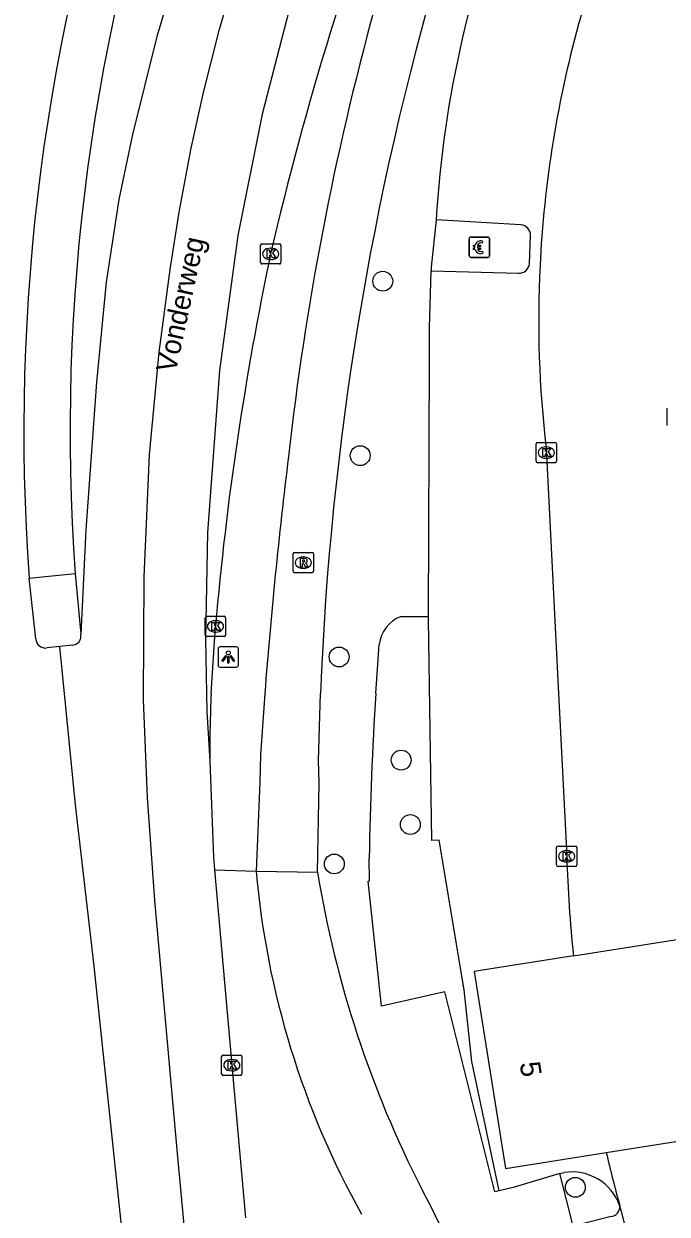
# Model space of a CAD drawing. Extents: x 160676 to 161153, y 383244 to 383713.
# Drawn here: x 160675.8 to 160707.5, y 383474.3 to 383533 of the extents above; entities that cross this region are included whole.
import ezdxf

# ---------------------------------------------------------------- set-up
doc = ezdxf.new("R2010")
doc.units = 0
for name, color, linetype in [('IMGEO_Berm_open', 7, 'Continuous'), ('IMGEO_Betaalautomaat', 7, 'Continuous'), ('IMGEO_Boom', 7, 'Continuous'), ('IMGEO_Fietspad_gesloten', 7, 'Continuous'), ('IMGEO_Kolk', 7, 'Continuous'), ('IMGEO_Lichtpunt', 7, 'Continuous'), ('IMGEO_Openbare_ruimte_label', 7, 'Continuous'), ('IMGEO_Pand', 7, 'Continuous'), ('IMGEO_Pand_nummerreeks', 7, 'Continuous'), ('IMGEO_Parkeervlak_open', 7, 'Continuous'), ('IMGEO_Rijbaan_lokaal_gesloten', 7, 'Continuous'), ('IMGEO_Rijbaan_lokaal_open', 7, 'Continuous'), ('IMGEO_Rioolput', 7, 'Continuous'), ('IMGEO_Verkeerseiland_open', 7, 'Continuous'), ('IMGEO_Voetpad_open', 7, 'Continuous')]:
    doc.layers.add(name, color=color, linetype=linetype)

msp = doc.modelspace()

# ---------------------------------------------------------------- linework, layer by layer
at = {"layer": 'IMGEO_Berm_open'}
msp.add_lwpolyline([(160685.215, 383491.312), (160687.262, 383491.252)], dxfattribs=at)
at = {"layer": 'IMGEO_Betaalautomaat'}
for p, q in [((160697.753, 383521.556), (160697.753, 383522.397)), ((160697.753, 383522.397), (160697.753, 383521.556)), ((160697.828, 383522.48), (160698.669, 383522.48)), ((160698.669, 383522.48), (160697.828, 383522.48)), ((160698.415, 383522.285), (160698.398, 383522.185)), ((160698.752, 383522.406), (160698.752, 383521.565)), ((160698.752, 383521.565), (160698.752, 383522.406)), ((160698.678, 383521.481), (160697.837, 383521.481)), ((160697.837, 383521.481), (160698.678, 383521.481)), ((160698.036, 383521.944), (160698.036, 383522.012)), ((160698.157, 383522.012), (160698.157, 383521.944)), ((160698.402, 383521.779), (160698.424, 383521.692))]:
    msp.add_line(p, q, dxfattribs=at)
for points in [[(160698.036, 383522.012), (160697.967, 383522.012), (160697.967, 383522.081), (160698.046, 383522.081)], [(160698.168, 383522.081), (160698.315, 383522.081), (160698.315, 383522.012), (160698.157, 383522.012)], [(160698.041, 383521.875), (160697.967, 383521.875), (160697.967, 383521.944), (160698.036, 383521.944)], [(160698.157, 383521.944), (160698.315, 383521.944), (160698.315, 383521.875), (160698.171, 383521.875)]]:
    msp.add_lwpolyline(points, dxfattribs=at)
for centre, radius, start, end in [((160697.831, 383522.403), 0.0779, 92.4484, 184.28452), ((160697.831, 383522.403), 0.0779, 92.4484, 184.28452), ((160698.329, 383522.005), 0.293, 73.01398, 165.01395), ((160698.335, 383522.018), 0.179, 69.32359, 159.56827), ((160698.675, 383522.403), 0.0779, 2.4484, 94.28452), ((160698.675, 383522.403), 0.0779, 2.4484, 94.28452), ((160697.831, 383521.559), 0.0779, 182.4484, 274.28452), ((160697.831, 383521.559), 0.0779, 182.4484, 274.28452), ((160698.302, 383521.93), 0.267, 191.80956, 297.03891), ((160698.335, 383521.945), 0.179, 202.76249, 291.86925), ((160698.675, 383521.559), 0.0779, 272.4484, 4.28452), ((160698.675, 383521.559), 0.0779, 272.4484, 4.28452)]:
    msp.add_arc(centre, radius, start, end, dxfattribs=at)
at = {"layer": 'IMGEO_Boom'}
for centre in [(160693.495, 383520.307), (160692.384, 383511.714), (160691.345, 383501.797), (160694.402, 383496.716), (160694.855, 383493.542), (160691.108, 383491.601), (160702.982, 383475.67)]:
    msp.add_circle(centre, 0.489, dxfattribs=at)
at = {"layer": 'IMGEO_Fietspad_gesloten'}
for points in [[(160687.684, 383500), (160687.47, 383496.982), (160687.435, 383495.626), (160687.262, 383491.252)], [(160690.28, 383491.194), (160690.363, 383495.591), (160690.332, 383496.702), (160690.426, 383500)], [(160687.262, 383491.252), (160690.28, 383491.194)]]:
    msp.add_lwpolyline(points, dxfattribs=at)
for centre, radius, start, end in [((160830.886, 383495.869), 142.908, 155.6296, 173.65091), ((160839.463, 383494.069), 149.155, 163.61031, 177.72109), ((160940.668, 383480.517), 253.733, 172.94675, 175.59611), ((160729.158, 383494.859), 42.051, 184.92047, 209.19494), ((160742.86, 383499.837), 53.286, 189.3349, 207.04462), ((160656.668, 383454.622), 44.053, 18.23874, 28.45013)]:
    msp.add_arc(centre, radius, start, end, dxfattribs=at)
at = {"layer": 'IMGEO_Kolk'}
for p, q in [((160687.477, 383521.229), (160687.477, 383522.081)), ((160687.552, 383522.155), (160688.404, 383522.155)), ((160688.478, 383522.081), (160688.478, 383521.229)), ((160687.965, 383521.935), (160687.99, 383521.935)), ((160688.404, 383521.155), (160687.552, 383521.155)), ((160687.988, 383521.375), (160687.963, 383521.375)), ((160707.505, 383513.202), (160707.505, 383514.054)), ((160701.051, 383511.438), (160701.051, 383512.29)), ((160701.126, 383512.364), (160701.978, 383512.364)), ((160701.539, 383512.144), (160701.564, 383512.144)), ((160702.052, 383512.29), (160702.052, 383511.438)), ((160701.562, 383511.584), (160701.537, 383511.584)), ((160701.978, 383511.364), (160701.126, 383511.364)), ((160684.755, 383502.876), (160684.755, 383503.728)), ((160684.83, 383503.802), (160685.682, 383503.802)), ((160685.243, 383503.582), (160685.268, 383503.582)), ((160685.756, 383503.728), (160685.756, 383502.876)), ((160685.682, 383502.802), (160684.83, 383502.802)), ((160685.266, 383503.022), (160685.241, 383503.022)), ((160702.053, 383491.551), (160702.053, 383492.403)), ((160702.128, 383492.477), (160702.98, 383492.477)), ((160702.541, 383492.257), (160702.566, 383492.257)), ((160703.054, 383492.403), (160703.054, 383491.551)), ((160702.564, 383491.697), (160702.539, 383491.697)), ((160702.98, 383491.477), (160702.128, 383491.477)), ((160685.634, 383482.187), (160686.486, 383482.187)), ((160685.559, 383481.261), (160685.559, 383482.113)), ((160686.047, 383481.967), (160686.072, 383481.967)), ((160686.56, 383482.113), (160686.56, 383481.261)), ((160686.486, 383481.187), (160685.634, 383481.187)), ((160686.07, 383481.407), (160686.045, 383481.407))]:
    msp.add_line(p, q, dxfattribs=at)
for points in [[(160687.477, 383521.229), (160687.477, 383522.081)], [(160687.552, 383522.155), (160688.404, 383522.155)], [(160688.478, 383522.081), (160688.478, 383521.229)], [(160687.798, 383521.855), (160687.921, 383521.855), (160687.921, 383521.704), (160688.051, 383521.855), (160688.215, 383521.855), (160688.069, 383521.704), (160688.222, 383521.455), (160688.07, 383521.455), (160687.985, 383521.619), (160687.921, 383521.552), (160687.921, 383521.455), (160687.798, 383521.455), (160687.798, 383521.855)], [(160688.404, 383521.155), (160687.552, 383521.155)], [(160707.505, 383513.202), (160707.505, 383514.054)], [(160701.051, 383511.438), (160701.051, 383512.29)], [(160701.126, 383512.364), (160701.978, 383512.364)], [(160701.372, 383512.064), (160701.495, 383512.064), (160701.495, 383511.913), (160701.625, 383512.064), (160701.789, 383512.064), (160701.643, 383511.913), (160701.796, 383511.664), (160701.644, 383511.664), (160701.559, 383511.828), (160701.495, 383511.761), (160701.495, 383511.664), (160701.372, 383511.664), (160701.372, 383512.064)], [(160702.052, 383512.29), (160702.052, 383511.438)], [(160701.978, 383511.364), (160701.126, 383511.364)], [(160684.755, 383502.876), (160684.755, 383503.728)], [(160684.83, 383503.802), (160685.682, 383503.802)], [(160685.076, 383503.502), (160685.199, 383503.502), (160685.199, 383503.351), (160685.329, 383503.502), (160685.493, 383503.502), (160685.347, 383503.351), (160685.5, 383503.102), (160685.348, 383503.102), (160685.263, 383503.266), (160685.199, 383503.199), (160685.199, 383503.102), (160685.076, 383503.102), (160685.076, 383503.502)], [(160685.756, 383503.728), (160685.756, 383502.876)], [(160685.682, 383502.802), (160684.83, 383502.802)], [(160702.053, 383491.551), (160702.053, 383492.403)], [(160702.128, 383492.477), (160702.98, 383492.477)], [(160702.374, 383492.177), (160702.497, 383492.177), (160702.497, 383492.026), (160702.627, 383492.177), (160702.791, 383492.177), (160702.645, 383492.026), (160702.798, 383491.777), (160702.646, 383491.777), (160702.561, 383491.941), (160702.497, 383491.874), (160702.497, 383491.777), (160702.374, 383491.777), (160702.374, 383492.177)], [(160703.054, 383492.403), (160703.054, 383491.551)], [(160702.98, 383491.477), (160702.128, 383491.477)], [(160685.634, 383482.187), (160686.486, 383482.187)], [(160685.559, 383481.261), (160685.559, 383482.113)], [(160685.88, 383481.887), (160686.003, 383481.887), (160686.003, 383481.736), (160686.133, 383481.887), (160686.297, 383481.887), (160686.151, 383481.736), (160686.304, 383481.487), (160686.152, 383481.487), (160686.067, 383481.651), (160686.003, 383481.584), (160686.003, 383481.487), (160685.88, 383481.487), (160685.88, 383481.887)], [(160686.56, 383482.113), (160686.56, 383481.261)], [(160686.486, 383481.187), (160685.634, 383481.187)]]:
    msp.add_lwpolyline(points, dxfattribs=at)
for centre, start, end in [((160687.554, 383522.079), 91.55205, 178.44795), ((160687.554, 383522.079), 91.55205, 178.44795), ((160688.402, 383522.079), 1.55205, 88.44795), ((160688.402, 383522.079), 1.55205, 88.44795), ((160687.554, 383521.231), 181.55205, 268.44795), ((160687.554, 383521.231), 181.55205, 268.44795), ((160688.402, 383521.231), 271.55205, 358.44795), ((160688.402, 383521.231), 271.55205, 358.44795), ((160701.128, 383512.288), 91.55205, 178.44795), ((160701.128, 383512.288), 91.55205, 178.44795), ((160701.976, 383512.288), 1.55205, 88.44795), ((160701.976, 383512.288), 1.55205, 88.44795), ((160701.128, 383511.44), 181.55205, 268.44795), ((160701.128, 383511.44), 181.55205, 268.44795), ((160701.976, 383511.44), 271.55205, 358.44795), ((160701.976, 383511.44), 271.55205, 358.44795), ((160684.832, 383503.726), 91.55205, 178.44795), ((160684.832, 383503.726), 91.55205, 178.44795), ((160685.68, 383503.726), 1.55205, 88.44795), ((160685.68, 383503.726), 1.55205, 88.44795), ((160684.832, 383502.878), 181.55205, 268.44795), ((160684.832, 383502.878), 181.55205, 268.44795), ((160685.68, 383502.878), 271.55205, 358.44795), ((160685.68, 383502.878), 271.55205, 358.44795), ((160702.13, 383492.401), 91.55205, 178.44795), ((160702.13, 383492.401), 91.55205, 178.44795), ((160702.978, 383492.401), 1.55205, 88.44795), ((160702.978, 383492.401), 1.55205, 88.44795), ((160702.13, 383491.553), 181.55205, 268.44795), ((160702.13, 383491.553), 181.55205, 268.44795), ((160702.978, 383491.553), 271.55205, 358.44795), ((160702.978, 383491.553), 271.55205, 358.44795), ((160685.636, 383482.111), 91.55205, 178.44795), ((160685.636, 383482.111), 91.55205, 178.44795), ((160686.484, 383482.111), 1.55205, 88.44795), ((160686.484, 383482.111), 1.55205, 88.44795), ((160685.636, 383481.263), 181.55205, 268.44795), ((160685.636, 383481.263), 181.55205, 268.44795), ((160686.484, 383481.263), 271.55205, 358.44795), ((160686.484, 383481.263), 271.55205, 358.44795)]:
    msp.add_arc(centre, 0.0765, start, end, dxfattribs=at)
for centre, major_axis, ratio, start_param, end_param in [((160687.964, 383521.655), (-0.387, 0.002), 0.722429, 4.712389, 7.853982), ((160687.989, 383521.655), (-0.39, 0.002), 0.717154, 1.570796, 4.712389), ((160701.538, 383511.864), (-0.387, 0.002), 0.722429, 4.712389, 7.853982), ((160701.563, 383511.864), (-0.39, 0.002), 0.717154, 1.570796, 4.712389), ((160685.242, 383503.302), (-0.387, 0.002), 0.722429, 4.712389, 7.853982), ((160685.267, 383503.302), (-0.39, 0.002), 0.717154, 1.570796, 4.712389), ((160702.54, 383491.977), (-0.387, 0.002), 0.722429, 4.712389, 7.853982), ((160702.565, 383491.977), (-0.39, 0.002), 0.717154, 1.570796, 4.712389), ((160686.046, 383481.687), (-0.387, 0.002), 0.722429, 4.712389, 7.853982), ((160686.071, 383481.687), (-0.39, 0.002), 0.717154, 1.570796, 4.712389)]:
    msp.add_ellipse(centre, major_axis=major_axis, ratio=ratio, start_param=start_param, end_param=end_param, dxfattribs=at)
at = {"layer": 'IMGEO_Lichtpunt'}
for p, q in [((160685.385, 383502.2), (160685.385, 383501.393)), ((160685.385, 383502.2), (160685.385, 383501.393)), ((160686.287, 383502.295), (160685.479, 383502.295)), ((160686.287, 383502.295), (160685.479, 383502.295)), ((160686.381, 383501.393), (160686.381, 383502.2)), ((160686.381, 383501.393), (160686.381, 383502.2)), ((160685.479, 383501.299), (160686.287, 383501.299)), ((160685.479, 383501.299), (160686.287, 383501.299))]:
    msp.add_line(p, q, dxfattribs=at)
for points in [[(160685.759, 383501.864), (160685.798, 383501.836), (160685.61, 383501.574), (160685.572, 383501.601), (160685.759, 383501.864)], [(160685.861, 383501.816), (160685.908, 383501.816), (160685.908, 383501.494), (160685.861, 383501.494), (160685.861, 383501.816)], [(160685.971, 383501.836), (160686.009, 383501.863), (160686.196, 383501.601), (160686.157, 383501.573), (160685.971, 383501.836)]]:
    msp.add_lwpolyline(points, dxfattribs=at)
msp.add_circle((160685.884, 383501.998), 0.0994, dxfattribs=at)
for centre, start, end in [((160685.479, 383502.2), 90, 180), ((160685.479, 383502.2), 90, 180), ((160686.287, 383502.2), 0, 90), ((160686.287, 383502.2), 0, 90), ((160685.479, 383501.393), 180, 270), ((160685.479, 383501.393), 180, 270), ((160686.287, 383501.393), 270, 0), ((160686.287, 383501.393), 270, 360)]:
    msp.add_arc(centre, 0.0946, start, end, dxfattribs=at)
at = {"layer": 'IMGEO_Pand'}
for points in [[(160702.884, 383487.072), (160709.132, 383488.067)], [(160702.884, 383487.072), (160698.001, 383486.295), (160699.544, 383476.6), (160704.503, 383477.389)], [(160704.503, 383477.389), (160709.795, 383478.231)]]:
    msp.add_lwpolyline(points, dxfattribs=at)
at = {"layer": 'IMGEO_Parkeervlak_open'}
for points in [[(160700.297, 383523.084), (160696.12, 383523.335)], [(160700.718, 383521.167), (160700.775, 383522.555)], [(160695.873, 383520.826), (160700.187, 383520.697)], [(160699.23, 383475.493), (160697.887, 383481.87), (160697.5, 383485.396), (160696.281, 383492.774), (160695.913, 383492.755), (160695.755, 383503.66), (160695.755, 383503.793)], [(160702.218, 383476.346), (160702.426, 383476.395)]]:
    msp.add_lwpolyline(points, dxfattribs=at)
for centre, radius, start, end in [((160700.247, 383522.558), 0.528, 359.65408, 84.54733), ((160700.205, 383521.212), 0.515, 268.04405, 354.98148), ((160778.529, 383494.844), 76.056, 193.26771, 195.32407), ((160702.817, 383473.93), 2.496, 19.03637, 99.02387)]:
    msp.add_arc(centre, radius, start, end, dxfattribs=at)
at = {"layer": 'IMGEO_Rijbaan_lokaal_gesloten'}
for points in [[(160723.044, 383600.836), (160719.324, 383596.439), (160713.063, 383589.27), (160709.696, 383585.215), (160705.6, 383580.218), (160702.963, 383576.838), (160700.534, 383573.501), (160696.741, 383567.566), (160694.147, 383562.923), (160691.409, 383557.397), (160688.975, 383551.769), (160686.454, 383545.185), (160684.145, 383538.275), (160682.371, 383532.368), (160681.16, 383527.53), (160680.501, 383524.333), (160679.874, 383520.258), (160679.388, 383515.338), (160678.873, 383508.063), (160678.616, 383502.924)], [(160727.682, 383597.073), (160717.292, 383585.599), (160710.987, 383578.024), (160707.499, 383573.354), (160704.487, 383569.021), (160701.37, 383563.93), (160698.475, 383558.64), (160695.509, 383552.532), (160692.543, 383545.152), (160690.79, 383540.075), (160689.355, 383535.536), (160687.563, 383528.543), (160686.35, 383522.561), (160685.459, 383515.912), (160684.867, 383507.93), (160684.757, 383502.656), (160684.835, 383499.113), (160684.974, 383496.66)], [(160687.968, 383428.367), (160683.396, 383477.158), (160682.26, 383489.795), (160681.902, 383494.869), (160681.705, 383499.702), (160681.744, 383505.743), (160682.012, 383511.753), (160682.478, 383516.818), (160683.016, 383520.889), (160683.468, 383523.707), (160684.062, 383526.862), (160684.662, 383529.599), (160685.454, 383532.715), (160686.021, 383534.678)], [(160676.413, 383502.683), (160676.076, 383505.674)], [(160678.343, 383505.911), (160678.616, 383502.924)], [(160685.04, 383500), (160685.251, 383503.301)], [(160677.594, 383502.312), (160676.94, 383502.24)], [(160678.192, 383502.378), (160677.594, 383502.312)], [(160688.615, 383388.908), (160686.903, 383407.316), (160685.127, 383426.54), (160683.55, 383442.888), (160682.063, 383458.998), (160680.726, 383472.857), (160679.265, 383486.721), (160678.36, 383494.517), (160677.594, 383502.312)], [(160684.974, 383496.66), (160685.161, 383491.941), (160685.215, 383491.312)], [(160685.215, 383491.312), (160686.06, 383481.687), (160686.733, 383474.175)]]:
    msp.add_lwpolyline(points, dxfattribs=at)
for centre, radius, start, end in [((160775.631, 383512.902), 99.817, 161.11345, 184.15236), ((160775.752, 383512.9), 97.66, 160.64672, 184.10411), ((160845.62, 383485.049), 161.841, 158.93806, 166.92747), ((160839.036, 383489.873), 154.37, 168.11876, 175.00965), ((160676.88, 383502.704), 0.468, 182.53712, 277.36158), ((160678.179, 383502.825), 0.448, 271.61381, 12.72345), ((160758.418, 383496.879), 73.445, 177.56478, 180.17113)]:
    msp.add_arc(centre, radius, start, end, dxfattribs=at)
at = {"layer": 'IMGEO_Rijbaan_lokaal_open'}
for points in [[(160701.303, 383522.149), (160701.241, 383521.08)], [(160701.542, 383512.084), (160702.151, 383500), (160702.555, 383491.973)]]:
    msp.add_lwpolyline(points, dxfattribs=at)
for centre, radius, start, end in [((160756.116, 383518.41), 54.94, 162.99017, 176.09775), ((160756.13, 383518.414), 54.954, 177.2188, 186.61392), ((160776.861, 383494.5), 74.349, 181.94743, 185.73348)]:
    msp.add_arc(centre, radius, start, end, dxfattribs=at)
at = {"layer": 'IMGEO_Rioolput'}
for p, q in [((160689.082, 383506.019), (160689.082, 383506.871)), ((160689.157, 383506.945), (160690.009, 383506.945)), ((160690.083, 383506.871), (160690.083, 383506.019)), ((160689.57, 383506.725), (160689.595, 383506.725)), ((160690.009, 383505.945), (160689.157, 383505.945)), ((160689.593, 383506.165), (160689.568, 383506.165))]:
    msp.add_line(p, q, dxfattribs=at)
for points in [[(160689.082, 383506.019), (160689.082, 383506.871)], [(160689.157, 383506.945), (160690.009, 383506.945)], [(160690.083, 383506.871), (160690.083, 383506.019)], [(160689.671, 383506.643), (160689.419, 383506.645), (160689.419, 383506.245)], [(160689.419, 383506.245), (160689.543, 383506.245), (160689.543, 383506.407), (160689.554, 383506.407)], [(160689.597, 383506.564), (160689.543, 383506.564), (160689.543, 383506.483)], [(160689.543, 383506.483), (160689.595, 383506.483)], [(160689.601, 383506.378), (160689.672, 383506.245), (160689.812, 383506.245), (160689.747, 383506.371)], [(160690.009, 383505.945), (160689.157, 383505.945)]]:
    msp.add_lwpolyline(points, dxfattribs=at)
for centre, radius, start, end in [((160689.159, 383506.869), 0.0765, 91.55205, 178.44795), ((160689.159, 383506.869), 0.0765, 91.55205, 178.44795), ((160690.007, 383506.869), 0.0765, 1.55205, 88.44795), ((160690.007, 383506.869), 0.0765, 1.55205, 88.44795), ((160689.553, 383506.354), 0.0533, 26.02933, 88.69889), ((160689.579, 383506.672), 0.19, 274.7715, 282.96867), ((160689.603, 383506.468), 0.0964, 77.00612, 93.18647), ((160689.617, 383506.525), 0.0378, 276.66336, 79.67722), ((160689.67, 383506.533), 0.109, 350.36119, 89.41601), ((160689.668, 383506.533), 0.112, 277.58423, 350.98172), ((160689.652, 383506.318), 0.108, 29.51342, 73.79051), ((160689.159, 383506.021), 0.0765, 181.55205, 268.44795), ((160689.159, 383506.021), 0.0765, 181.55205, 268.44795), ((160690.007, 383506.021), 0.0765, 271.55205, 358.44795), ((160690.007, 383506.021), 0.0765, 271.55205, 358.44795)]:
    msp.add_arc(centre, radius, start, end, dxfattribs=at)
for centre, major_axis, ratio, start_param, end_param in [((160689.569, 383506.445), (-0.387, 0.002), 0.722429, 4.712389, 7.853982), ((160689.594, 383506.445), (-0.39, 0.002), 0.717154, 1.570796, 4.712389)]:
    msp.add_ellipse(centre, major_axis=major_axis, ratio=ratio, start_param=start_param, end_param=end_param, dxfattribs=at)
at = {"layer": 'IMGEO_Verkeerseiland_open'}
msp.add_lwpolyline([(160676.076, 383505.674), (160678.343, 383505.911)], dxfattribs=at)
at = {"layer": 'IMGEO_Voetpad_open'}
for points in [[(160696.12, 383523.335), (160695.878, 383520.992), (160695.873, 383520.826)], [(160695.755, 383503.793), (160695.791, 383516.533), (160695.791, 383518.013), (160695.873, 383520.826)], [(160694.386, 383503.797), (160695.755, 383503.793)], [(160693.151, 383500), (160693.325, 383502.405)], [(160699.23, 383475.493), (160699.019, 383475.443), (160696.549, 383485.302), (160693.427, 383484.601), (160692.77, 383490.76), (160692.834, 383490.761), (160692.83, 383491.882)], [(160702.218, 383476.346), (160699.925, 383475.656), (160699.23, 383475.493)], [(160704.742, 383474.226), (160702.882, 383473.753), (160702.218, 383476.346)], [(160707.356, 383466.299), (160705.266, 383474.42), (160705.177, 383474.744)]]:
    msp.add_lwpolyline(points, dxfattribs=at)
for centre, radius, start, end in [((160750.842, 383519.973), 54.825, 157.62632, 176.48438), ((160695.02, 383502.213), 1.706, 111.81761, 173.55218), ((160850.842, 383489.699), 158.027, 176.26262, 179.20858), ((160704.664, 383474.733), 0.513, 278.69665, 1.2584)]:
    msp.add_arc(centre, radius, start, end, dxfattribs=at)

# ---------------------------------------------------------------- texts
at = {"layer": 'IMGEO_Openbare_ruimte_label'}
msp.add_text('Vonderweg', height=1, rotation=77.75714, dxfattribs=at).set_placement((160683.289, 383515.758))
at = {"layer": 'IMGEO_Pand_nummerreeks'}
msp.add_text('5', height=1, rotation=278.84626, dxfattribs=at).set_placement((160700.238, 383481.789))

doc.saveas('drawing.dxf')
